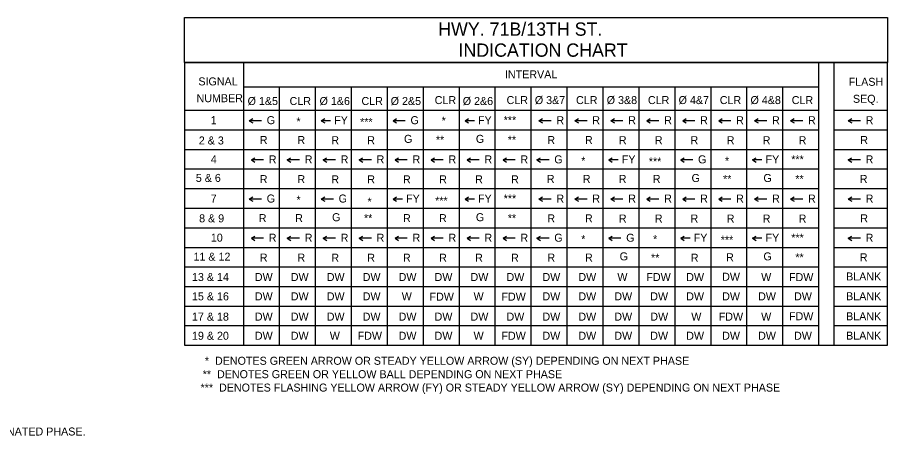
# Model space of a CAD drawing. Extents: x 1 to 35.4, y 0.4 to 10.6.
# Drawn here: x 26.67 to 35.36, y 0.63 to 4.82 of the extents above; entities that cross this region are included whole.
import ezdxf

# ---------------------------------------------------------------- set-up
doc = ezdxf.new("R2010")
doc.units = 0
for name, color, linetype in [('$', 7, 'Continuous'), ('base', 7, 'Continuous'), ('PHASE', 7, 'Continuous'), ('TBLBDR', 7, 'Continuous'), ('TBLLINE', 7, 'Continuous'), ('TBLTEXT', 7, 'Continuous'), ('TITEXT', 7, 'Continuous')]:
    doc.layers.add(name, color=color, linetype=linetype)

msp = doc.modelspace()

# ---------------------------------------------------------------- linework, layer by layer
at = {"layer": 'PHASE'}
for p, q in [((28.9848, 3.7816), (29.0197, 3.8036)), ((28.9848, 3.7816), (29.0197, 3.7596)), ((29.106, 3.7816), (28.9848, 3.7816)), ((29.703, 3.7816), (29.7379, 3.8036)), ((29.797, 3.7816), (29.703, 3.7816)), ((29.703, 3.7816), (29.7379, 3.7596)), ((30.4211, 3.7816), (30.456, 3.8036)), ((30.4211, 3.7816), (30.456, 3.7596)), ((30.5424, 3.7816), (30.4211, 3.7816)), ((31.1393, 3.7816), (31.1742, 3.8036)), ((31.2334, 3.7816), (31.1393, 3.7816)), ((31.1393, 3.7816), (31.1742, 3.7596)), ((31.8779, 3.7816), (31.9128, 3.8036)), ((31.8779, 3.7816), (31.9128, 3.7596)), ((31.9992, 3.7816), (31.8779, 3.7816)), ((32.237, 3.7816), (32.2719, 3.8036)), ((32.237, 3.7816), (32.2719, 3.7596)), ((32.3582, 3.7816), (32.237, 3.7816)), ((32.5961, 3.7816), (32.631, 3.8036)), ((32.5961, 3.7816), (32.631, 3.7596)), ((32.7173, 3.7816), (32.5961, 3.7816)), ((32.9552, 3.7816), (32.9901, 3.8036)), ((32.9552, 3.7816), (32.9901, 3.7596)), ((33.0764, 3.7816), (32.9552, 3.7816)), ((33.3143, 3.7816), (33.3492, 3.8036)), ((33.3143, 3.7816), (33.3492, 3.7596)), ((33.4355, 3.7816), (33.3143, 3.7816)), ((33.6734, 3.7816), (33.7083, 3.8036)), ((33.6734, 3.7816), (33.7083, 3.7596)), ((33.7946, 3.7816), (33.6734, 3.7816)), ((34.0324, 3.7816), (34.0673, 3.8036)), ((34.0324, 3.7816), (34.0673, 3.7596)), ((34.1537, 3.7816), (34.0324, 3.7816)), ((34.3915, 3.7816), (34.4264, 3.8036)), ((34.3915, 3.7816), (34.4264, 3.7596)), ((34.5127, 3.7816), (34.3915, 3.7816)), ((34.9676, 3.7816), (35.0025, 3.8036)), ((34.9676, 3.7816), (35.0025, 3.7596)), ((35.0888, 3.7816), (34.9676, 3.7816)), ((29.0053, 3.3899), (29.0402, 3.4119)), ((29.3644, 3.3899), (29.3993, 3.4119)), ((29.7235, 3.3899), (29.7583, 3.4119)), ((30.0825, 3.3899), (30.1174, 3.4119)), ((30.4416, 3.3899), (30.4765, 3.4119)), ((30.8007, 3.3899), (30.8356, 3.4119)), ((31.1598, 3.3899), (31.1947, 3.4119)), ((31.5189, 3.3899), (31.5538, 3.4119)), ((31.8575, 3.3899), (31.8924, 3.4119)), ((32.5756, 3.3899), (32.6105, 3.4119)), ((33.2938, 3.3899), (33.3287, 3.4119)), ((34.012, 3.3899), (34.0469, 3.4119)), ((34.9676, 3.3899), (35.0025, 3.4119)), ((29.0053, 3.3899), (29.0402, 3.3679)), ((29.1265, 3.3899), (29.0053, 3.3899)), ((29.3644, 3.3899), (29.3993, 3.3679)), ((29.4856, 3.3899), (29.3644, 3.3899)), ((29.7235, 3.3899), (29.7583, 3.3679)), ((29.8447, 3.3899), (29.7235, 3.3899)), ((30.0825, 3.3899), (30.1174, 3.3679)), ((30.2038, 3.3899), (30.0825, 3.3899)), ((30.4416, 3.3899), (30.4765, 3.3679)), ((30.5628, 3.3899), (30.4416, 3.3899)), ((30.8007, 3.3899), (30.8356, 3.3679)), ((30.9219, 3.3899), (30.8007, 3.3899)), ((31.1598, 3.3899), (31.1947, 3.3679)), ((31.281, 3.3899), (31.1598, 3.3899)), ((31.5189, 3.3899), (31.5538, 3.3679)), ((31.6401, 3.3899), (31.5189, 3.3899)), ((31.8575, 3.3899), (31.8924, 3.3679)), ((31.9787, 3.3899), (31.8575, 3.3899)), ((32.6697, 3.3899), (32.5756, 3.3899)), ((32.5756, 3.3899), (32.6105, 3.3679)), ((33.2938, 3.3899), (33.3287, 3.3679)), ((33.415, 3.3899), (33.2938, 3.3899)), ((34.106, 3.3899), (34.012, 3.3899)), ((34.012, 3.3899), (34.0469, 3.3679)), ((34.9676, 3.3899), (35.0025, 3.3679)), ((35.0888, 3.3899), (34.9676, 3.3899)), ((28.9848, 2.9982), (29.0197, 3.0202)), ((28.9848, 2.9982), (29.0197, 2.9762)), ((29.106, 2.9982), (28.9848, 2.9982)), ((29.703, 2.9982), (29.7379, 3.0202)), ((29.703, 2.9982), (29.7379, 2.9762)), ((29.8242, 2.9982), (29.703, 2.9982)), ((30.4211, 2.9982), (30.456, 3.0202)), ((30.5152, 2.9982), (30.4211, 2.9982)), ((30.4211, 2.9982), (30.456, 2.9762)), ((31.1393, 2.9982), (31.1742, 3.0202)), ((31.2334, 2.9982), (31.1393, 2.9982)), ((31.1393, 2.9982), (31.1742, 2.9762)), ((31.8779, 2.9982), (31.9128, 3.0202)), ((31.8779, 2.9982), (31.9128, 2.9762)), ((31.9992, 2.9982), (31.8779, 2.9982)), ((32.237, 2.9982), (32.2719, 3.0202)), ((32.237, 2.9982), (32.2719, 2.9762)), ((32.3582, 2.9982), (32.237, 2.9982)), ((32.5961, 2.9982), (32.631, 3.0202)), ((32.5961, 2.9982), (32.631, 2.9762)), ((32.7173, 2.9982), (32.5961, 2.9982)), ((32.9552, 2.9982), (32.9901, 3.0202)), ((32.9552, 2.9982), (32.9901, 2.9762)), ((33.0764, 2.9982), (32.9552, 2.9982)), ((33.3143, 2.9982), (33.3492, 3.0202)), ((33.3143, 2.9982), (33.3492, 2.9762)), ((33.4355, 2.9982), (33.3143, 2.9982)), ((33.6734, 2.9982), (33.7083, 3.0202)), ((33.6734, 2.9982), (33.7083, 2.9762)), ((33.7946, 2.9982), (33.6734, 2.9982)), ((34.0324, 2.9982), (34.0673, 3.0202)), ((34.0324, 2.9982), (34.0673, 2.9762)), ((34.1537, 2.9982), (34.0324, 2.9982)), ((34.3915, 2.9982), (34.4264, 3.0202)), ((34.3915, 2.9982), (34.4264, 2.9762)), ((34.5127, 2.9982), (34.3915, 2.9982)), ((34.9676, 2.9982), (35.0025, 3.0202)), ((34.9676, 2.9982), (35.0025, 2.9762)), ((35.0888, 2.9982), (34.9676, 2.9982)), ((29.0053, 2.6065), (29.0402, 2.6285)), ((29.3644, 2.6065), (29.3993, 2.6285)), ((29.7235, 2.6065), (29.7583, 2.6285)), ((30.0825, 2.6065), (30.1174, 2.6285)), ((30.4416, 2.6065), (30.4765, 2.6285)), ((30.8007, 2.6065), (30.8356, 2.6285)), ((31.1598, 2.6065), (31.1947, 2.6285)), ((31.5189, 2.6065), (31.5538, 2.6285)), ((31.8575, 2.6065), (31.8924, 2.6285)), ((32.5756, 2.6065), (32.6105, 2.6285)), ((33.2938, 2.6065), (33.3287, 2.6285)), ((34.012, 2.6065), (34.0469, 2.6285)), ((34.9676, 2.6065), (35.0025, 2.6285)), ((29.0053, 2.6065), (29.0402, 2.5845)), ((29.1265, 2.6065), (29.0053, 2.6065)), ((29.3644, 2.6065), (29.3993, 2.5845)), ((29.4856, 2.6065), (29.3644, 2.6065)), ((29.7235, 2.6065), (29.7583, 2.5845)), ((29.8447, 2.6065), (29.7235, 2.6065)), ((30.0825, 2.6065), (30.1174, 2.5845)), ((30.2038, 2.6065), (30.0825, 2.6065)), ((30.4416, 2.6065), (30.4765, 2.5845)), ((30.5628, 2.6065), (30.4416, 2.6065)), ((30.8007, 2.6065), (30.8356, 2.5845)), ((30.9219, 2.6065), (30.8007, 2.6065)), ((31.1598, 2.6065), (31.1947, 2.5845)), ((31.281, 2.6065), (31.1598, 2.6065)), ((31.5189, 2.6065), (31.5538, 2.5845)), ((31.6401, 2.6065), (31.5189, 2.6065)), ((31.8575, 2.6065), (31.8924, 2.5845)), ((31.9787, 2.6065), (31.8575, 2.6065)), ((32.5756, 2.6065), (32.6105, 2.5845)), ((32.6969, 2.6065), (32.5756, 2.6065)), ((33.3879, 2.6065), (33.2938, 2.6065)), ((33.2938, 2.6065), (33.3287, 2.5845)), ((34.106, 2.6065), (34.012, 2.6065)), ((34.012, 2.6065), (34.0469, 2.5845)), ((34.9676, 2.6065), (35.0025, 2.5845)), ((35.0888, 2.6065), (34.9676, 2.6065))]:
    msp.add_line(p, q, dxfattribs=at)
at = {"layer": 'TBLBDR'}
for p, q in [((28.3384, 4.3638), (28.3384, 2.43)), ((28.3384, 4.3638), (35.3607, 4.3638)), ((28.9286, 2.3203), (28.9286, 4.3638)), ((34.6739, 1.5376), (34.6739, 4.3638)), ((34.8248, 4.3638), (34.8248, 2.431)), ((35.3607, 1.5376), (35.3607, 4.3638)), ((31.8012, 2.3203), (31.8012, 4.1204)), ((28.3384, 3.887), (34.6739, 3.887)), ((28.3384, 3.887), (30.6426, 3.887)), ((34.8248, 3.887), (35.3607, 3.887)), ((28.3384, 2.43), (28.3384, 2.3203)), ((34.8248, 2.43), (34.8248, 2.321)), ((28.3384, 2.321), (34.6739, 2.321)), ((28.3384, 2.321), (28.3384, 1.5376)), ((28.9286, 1.5376), (28.9286, 2.321)), ((31.8012, 1.5376), (31.8012, 2.321)), ((34.8248, 2.321), (35.3607, 2.321)), ((34.8248, 2.321), (34.8248, 1.5401)), ((28.3384, 1.5376), (35.3607, 1.5376))]:
    msp.add_line(p, q, dxfattribs=at)
msp.add_lwpolyline([(28.3384, 4.8154), (35.3607, 4.8154), (35.3607, 4.3638), (28.3384, 4.3638)], close=True, dxfattribs=at)
at = {"layer": 'TBLLINE'}
for p, q in [((28.9286, 4.1204), (34.6739, 4.1204)), ((29.2877, 2.3203), (29.2877, 4.1204)), ((29.6467, 2.3203), (29.6467, 4.1204)), ((30.0058, 2.3203), (30.0058, 4.1204)), ((30.3649, 2.3203), (30.3649, 4.1204)), ((30.724, 2.3203), (30.724, 4.1204)), ((31.0831, 2.3203), (31.0831, 4.1204)), ((31.4421, 2.3203), (31.4421, 4.1204)), ((32.1603, 2.3203), (32.1603, 4.1204)), ((32.5194, 1.5376), (32.5194, 4.1204)), ((32.8785, 1.5376), (32.8785, 4.1204)), ((33.2376, 1.5376), (33.2376, 4.1204)), ((33.5966, 1.5376), (33.5966, 4.1204)), ((33.9557, 2.3203), (33.9557, 4.1204)), ((34.3148, 2.3203), (34.3148, 4.1204)), ((28.3384, 3.6912), (34.6739, 3.6912)), ((34.8248, 3.6912), (35.3607, 3.6912)), ((28.3384, 3.4953), (34.6739, 3.4953)), ((34.8248, 3.4953), (35.3607, 3.4953)), ((28.3384, 3.2995), (34.6739, 3.2995)), ((34.8248, 3.2995), (35.3607, 3.2995)), ((28.3384, 3.1037), (34.6739, 3.1037)), ((34.8248, 3.1037), (35.3607, 3.1037)), ((28.3384, 2.9078), (34.6739, 2.9078)), ((34.8248, 2.9078), (35.3607, 2.9078)), ((28.3384, 2.712), (34.6739, 2.712)), ((34.8248, 2.7116), (35.3607, 2.7116)), ((28.3384, 2.5161), (34.6739, 2.5161)), ((34.8248, 2.5161), (35.3607, 2.5161)), ((29.2877, 1.5376), (29.2877, 2.321)), ((29.6467, 1.5376), (29.6467, 2.321)), ((30.0058, 1.5376), (30.0058, 2.321)), ((30.3649, 1.5376), (30.3649, 2.321)), ((30.724, 1.5376), (30.724, 2.321)), ((31.0831, 1.5376), (31.0831, 2.321)), ((31.4421, 1.5376), (31.4421, 2.321)), ((32.1603, 1.5376), (32.1603, 2.321)), ((33.9557, 1.5376), (33.9557, 2.321)), ((34.3148, 1.5376), (34.3148, 2.321)), ((28.3384, 2.1252), (34.6739, 2.1252)), ((34.8248, 2.1252), (35.3607, 2.1252)), ((28.3384, 1.9293), (34.6739, 1.9293)), ((34.8248, 1.9293), (35.3607, 1.9293)), ((28.3384, 1.7335), (34.6739, 1.7335)), ((34.8248, 1.7335), (35.3607, 1.7335))]:
    msp.add_line(p, q, dxfattribs=at)

# ---------------------------------------------------------------- texts
at = {"layer": '$'}
msp.add_text('HWY. 71B/13TH ST.', height=0.133, dxfattribs=at).set_placement((30.871, 4.6316))
at = {"layer": 'base'}
msp.add_text('INDICATION CHART', height=0.133, dxfattribs=at).set_placement((31.0743, 4.4217))
at = {"layer": 'TBLTEXT'}
for s, height, p in [('1', 0.08, (28.5992, 3.7477)), ('G', 0.08, (29.1585, 3.7474)), ('FY', 0.08, (29.8328, 3.7474)), ('G', 0.08, (30.5949, 3.7474)), ('FY', 0.08, (31.2691, 3.7474)), ('***', 0.08, (31.5256, 3.7481)), ('R', 0.08, (32.0517, 3.7474)), ('R', 0.08, (32.4107, 3.7474)), ('R', 0.08, (32.7698, 3.7474)), ('R', 0.08, (33.1289, 3.7474)), ('R', 0.08, (33.488, 3.7474)), ('R', 0.08, (33.8471, 3.7474)), ('R', 0.08, (34.2061, 3.7474)), ('R', 0.08, (34.5652, 3.7474)), ('R', 0.08, (35.1413, 3.7474)), ('*', 0.08, (29.4562, 3.7349)), ('***', 0.08, (30.0912, 3.7304)), ('*', 0.08, (30.9061, 3.7439)), ('2 & 3', 0.08, (28.4799, 3.5448)), ('R', 0.08, (29.0892, 3.5493)), ('R', 0.08, (29.4649, 3.5493)), ('R', 0.08, (29.8038, 3.5475)), ('R', 0.08, (30.1629, 3.5475)), ('G', 0.08, (30.5297, 3.5607)), ('**', 0.08, (30.8483, 3.5518)), ('G', 0.08, (31.2479, 3.5607)), ('**', 0.08, (31.5664, 3.5518)), ('R', 0.08, (31.9619, 3.5493)), ('R', 0.08, (32.3376, 3.5493)), ('R', 0.08, (32.6765, 3.5475)), ('R', 0.08, (33.0356, 3.5475)), ('R', 0.08, (33.3923, 3.5475)), ('R', 0.08, (33.7537, 3.5475)), ('R', 0.08, (34.1128, 3.5475)), ('R', 0.08, (34.4719, 3.5475)), ('R', 0.08, (35.0878, 3.5493)), ('4', 0.08, (28.6001, 3.3565)), ('R', 0.08, (29.179, 3.3557)), ('R', 0.08, (29.5381, 3.3557)), ('R', 0.08, (29.8972, 3.3557)), ('R', 0.08, (30.2562, 3.3557)), ('R', 0.08, (30.6153, 3.3557)), ('R', 0.08, (30.9744, 3.3557)), ('R', 0.08, (31.3335, 3.3557)), ('R', 0.08, (31.6926, 3.3557)), ('G', 0.08, (32.0312, 3.3557)), ('*', 0.08, (32.2998, 3.3414)), ('FY', 0.08, (32.7054, 3.3557)), ('***', 0.08, (32.9758, 3.335)), ('G', 0.08, (33.4675, 3.3557)), ('*', 0.08, (33.7361, 3.3414)), ('FY', 0.08, (34.1417, 3.3557)), ('***', 0.08, (34.3982, 3.3564)), ('R', 0.08, (35.1413, 3.3557)), ('5 & 6', 0.08, (28.4503, 3.1703)), ('R', 0.08, (29.0892, 3.158)), ('R', 0.08, (29.4649, 3.158)), ('R', 0.08, (29.8038, 3.1562)), ('R', 0.08, (30.1629, 3.1562)), ('R', 0.08, (30.5196, 3.1562)), ('R', 0.08, (30.8811, 3.1562)), ('R', 0.08, (31.2402, 3.1562)), ('R', 0.08, (31.5992, 3.1562)), ('R', 0.08, (31.9566, 3.1602)), ('R', 0.08, (32.3157, 3.1602)), ('R', 0.08, (32.6748, 3.1602)), ('R', 0.08, (33.0148, 3.1604)), ('G', 0.08, (33.4024, 3.1694)), ('**', 0.08, (33.7172, 3.1602)), ('G', 0.08, (34.1205, 3.1694)), ('**', 0.08, (34.4391, 3.1604)), ('R', 0.08, (35.0829, 3.1599)), ('7', 0.08, (28.5992, 2.9644)), ('G', 0.08, (29.1585, 2.964)), ('G', 0.08, (29.8767, 2.964)), ('FY', 0.08, (30.5509, 2.964)), ('FY', 0.08, (31.2691, 2.964)), ('***', 0.08, (31.5256, 2.9647)), ('R', 0.08, (32.0517, 2.964)), ('R', 0.08, (32.4107, 2.964)), ('R', 0.08, (32.7698, 2.964)), ('R', 0.08, (33.1289, 2.964)), ('R', 0.08, (33.488, 2.964)), ('R', 0.08, (33.8471, 2.964)), ('R', 0.08, (34.2061, 2.964)), ('R', 0.08, (34.5652, 2.964)), ('R', 0.08, (35.1413, 2.964)), ('*', 0.08, (29.4562, 2.9515)), ('*', 0.08, (30.1653, 2.9334)), ('***', 0.08, (30.841, 2.9425)), ('8 & 9', 0.08, (28.4834, 2.7659)), ('R', 0.08, (29.0795, 2.7682)), ('R', 0.08, (29.443, 2.7682)), ('G', 0.08, (29.8116, 2.7773)), ('**', 0.08, (30.1301, 2.7684)), ('R', 0.08, (30.5203, 2.7682)), ('R', 0.08, (30.8794, 2.7682)), ('G', 0.08, (31.2479, 2.7773)), ('**', 0.08, (31.5664, 2.7684)), ('R', 0.08, (31.9619, 2.7659)), ('R', 0.08, (32.3376, 2.7659)), ('R', 0.08, (32.6765, 2.7641)), ('R', 0.08, (33.0356, 2.7641)), ('R', 0.08, (33.3923, 2.7641)), ('R', 0.08, (33.7537, 2.7641)), ('R', 0.08, (34.1128, 2.7641)), ('R', 0.08, (34.4719, 2.7641)), ('R', 0.08, (35.0878, 2.7659)), ('10', 0.08, (28.6001, 2.5731)), ('R', 0.08, (29.179, 2.5723)), ('R', 0.08, (29.5381, 2.5723)), ('R', 0.08, (29.8972, 2.5723)), ('R', 0.08, (30.2562, 2.5723)), ('R', 0.08, (30.6153, 2.5723)), ('R', 0.08, (30.9744, 2.5723)), ('R', 0.08, (31.3335, 2.5723)), ('R', 0.08, (31.6926, 2.5723)), ('G', 0.08, (32.0312, 2.5723)), ('*', 0.08, (32.2998, 2.558)), ('G', 0.08, (32.7493, 2.5723)), ('*', 0.08, (33.0179, 2.558)), ('FY', 0.08, (33.4236, 2.5723)), ('***', 0.08, (33.694, 2.5516)), ('FY', 0.08, (34.1417, 2.5723)), ('***', 0.08, (34.3982, 2.573)), ('R', 0.08, (35.1413, 2.5723)), ('11 & 12', 0.08, (28.4271, 2.3826)), ('R', 0.08, (29.0892, 2.3742)), ('R', 0.08, (29.4649, 2.3742)), ('R', 0.08, (29.8038, 2.3724)), ('R', 0.08, (30.1629, 2.3724)), ('R', 0.08, (30.5196, 2.3724)), ('R', 0.08, (30.8811, 2.3724)), ('R', 0.08, (31.2402, 2.3724)), ('R', 0.08, (31.5992, 2.3724)), ('R', 0.08, (31.9619, 2.3742)), ('R', 0.08, (32.3376, 2.3742)), ('G', 0.08, (32.6842, 2.3857)), ('**', 0.08, (32.9975, 2.3724)), ('R', 0.08, (33.3947, 2.3724)), ('R', 0.08, (33.7471, 2.3767)), ('G', 0.08, (34.1205, 2.3857)), ('**', 0.08, (34.4391, 2.3767)), ('R', 0.08, (35.0829, 2.3765)), ('13 & 14', 0.08, (28.412, 2.1795)), ('DW', 0.08, (33.708, 2.1819)), ('BLANK', 0.08, (34.9461, 2.1846)), ('DW', 0.08, (29.0399, 2.1795)), ('DW', 0.08, (29.399, 2.1795)), ('DW', 0.08, (29.7581, 2.1795)), ('DW', 0.08, (30.1172, 2.1795)), ('DW', 0.08, (30.4763, 2.1795)), ('DW', 0.08, (30.8353, 2.1795)), ('DW', 0.08, (31.1944, 2.1795)), ('DW', 0.08, (31.5535, 2.1795)), ('DW', 0.08, (31.9126, 2.1795)), ('DW', 0.08, (32.2717, 2.1795)), ('W', 0.08, (32.6612, 2.1795)), ('FDW', 0.08, (32.951, 2.1795)), ('DW', 0.08, (33.3489, 2.1788)), ('W', 0.08, (34.0976, 2.1795)), ('FDW', 0.08, (34.3756, 2.1783)), ('15 & 16', 0.08, (28.412, 1.9862)), ('DW', 0.08, (29.0399, 1.9862)), ('DW', 0.08, (29.399, 1.9862)), ('DW', 0.08, (29.7581, 1.9862)), ('DW', 0.08, (30.1172, 1.9862)), ('W', 0.08, (30.5068, 1.9862)), ('FDW', 0.08, (30.7847, 1.9831)), ('W', 0.08, (31.2249, 1.9862)), ('FDW', 0.08, (31.5029, 1.9831)), ('DW', 0.08, (31.9126, 1.9862)), ('DW', 0.08, (32.2717, 1.9862)), ('DW', 0.08, (32.6308, 1.9862)), ('DW', 0.08, (32.9898, 1.9862)), ('DW', 0.08, (33.3489, 1.9862)), ('DW', 0.08, (33.708, 1.9862)), ('DW', 0.08, (34.0671, 1.9862)), ('DW', 0.08, (34.4262, 1.9862)), ('BLANK', 0.08, (34.9461, 1.9873)), ('17 & 18', 0.08, (28.412, 1.7834)), ('DW', 0.08, (29.0399, 1.7834)), ('DW', 0.08, (29.399, 1.7834)), ('DW', 0.08, (29.7581, 1.7834)), ('DW', 0.08, (30.1172, 1.7834)), ('DW', 0.08, (30.4763, 1.7834)), ('DW', 0.08, (30.8353, 1.7834)), ('DW', 0.08, (31.1944, 1.7834)), ('DW', 0.08, (31.5535, 1.7834)), ('DW', 0.08, (31.9126, 1.7834)), ('DW', 0.08, (32.2717, 1.7834)), ('DW', 0.08, (32.6308, 1.7834)), ('DW', 0.08, (32.9903, 1.7834)), ('W', 0.08, (33.3994, 1.7834)), ('FDW', 0.08, (33.6739, 1.7834)), ('W', 0.08, (34.0976, 1.7834)), ('FDW', 0.08, (34.3756, 1.7873)), ('BLANK', 0.08, (34.9461, 1.7863)), ('19 & 20', 0.08, (28.412, 1.5922)), ('DW', 0.08, (29.0399, 1.5922)), ('DW', 0.08, (29.399, 1.5922)), ('W', 0.08, (29.7886, 1.5922)), ('FDW', 0.08, (30.0666, 1.5922)), ('DW', 0.08, (30.4763, 1.5922)), ('DW', 0.08, (30.8353, 1.5922)), ('W', 0.08, (31.2249, 1.5922)), ('FDW', 0.08, (31.5029, 1.5922)), ('DW', 0.08, (31.9126, 1.5922)), ('DW', 0.08, (32.2717, 1.5922)), ('DW', 0.08, (32.6308, 1.5922)), ('DW', 0.08, (32.9898, 1.5922)), ('DW', 0.08, (33.3489, 1.5922)), ('DW', 0.08, (33.708, 1.5922)), ('DW', 0.08, (34.0671, 1.5922)), ('DW', 0.08, (34.4262, 1.5922)), ('BLANK', 0.08, (34.9461, 1.5929)), ('  *  DENOTES GREEN ARROW OR STEADY YELLOW ARROW (SY) DEPENDING ON NEXT PHASE', 0.08, (28.4812, 1.342)), (' **  DENOTES GREEN OR YELLOW BALL DEPENDING ON NEXT PHASE', 0.08, (28.4895, 1.208)), ('***  DENOTES FLASHING YELLOW ARROW (FY) OR STEADY YELLOW ARROW (SY) DEPENDING ON NEXT PHASE', 0.08, (28.4978, 1.074)), ('THIS IS WIRED TO CONTROLLER INPUT DETECTOR NUMBER WHICH IS PROGRAMMED TO ACTUATE THE DESIGNATED PHASE.', 0.0799944, (20.7453, 0.6348))]:
    msp.add_text(s, height=height, dxfattribs=at).set_placement(p)
at = {"layer": 'TITEXT'}
for s, p in [('INTERVAL', (31.5382, 4.2058)), ('SIGNAL', (28.4759, 4.1352)), ('FLASH', (34.9717, 4.1313)), ('NUMBER', (28.4576, 3.9674)), ('%%C 1&5', (28.9677, 3.9391)), ('CLR', (29.387, 3.9391)), ('%%C 1&6', (29.6864, 3.9391)), ('CLR', (30.1052, 3.9391)), ('%%C 2&5', (30.397, 3.9391)), ('CLR', (30.8364, 3.9486)), ('%%C 2&6', (31.1167, 3.9391)), ('CLR', (31.5546, 3.9486)), ('%%C 3&7', (31.8368, 3.9486)), ('CLR', (32.2483, 3.9486)), ('%%C 3&8', (32.5549, 3.9486)), ('CLR', (32.9665, 3.9486)), ('%%C 4&7', (33.2731, 3.9486)), ('CLR', (33.6846, 3.9486)), ('%%C 4&8', (33.9913, 3.9486)), ('CLR', (34.4028, 3.9486)), ('SEQ.', (35.0144, 3.9613))]:
    msp.add_text(s, height=0.08, dxfattribs=at).set_placement(p)

doc.saveas('drawing.dxf')
